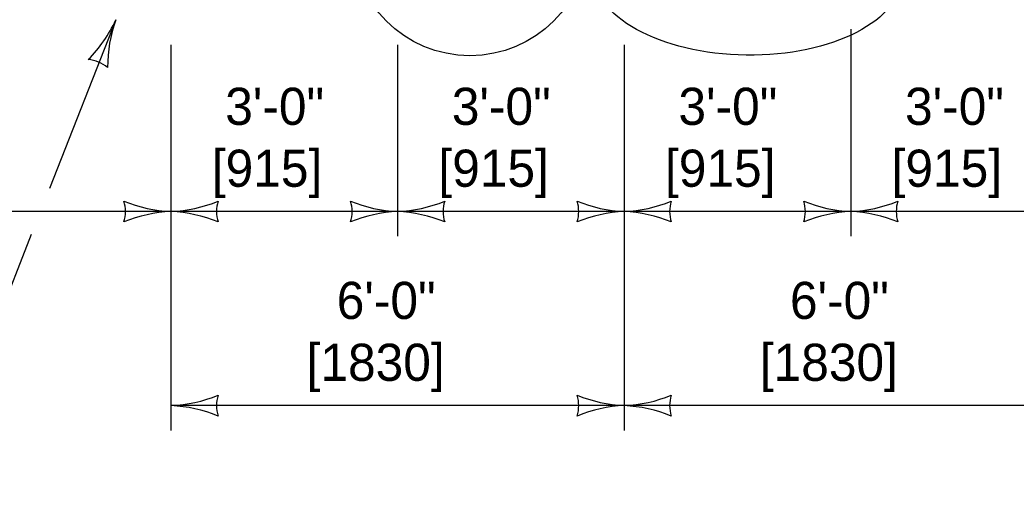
# Model space of a CAD drawing. Extents: x 49991.4 to 50021, y 49987.6 to 50011.4.
# Drawn here: x 50002.768 to 50004.377, y 49995.962 to 49996.713 of the extents above; entities that cross this region are included whole.
import ezdxf

# ---------------------------------------------------------------- set-up
doc = ezdxf.new("R2010")
doc.units = 0
for name, color, linetype in [('Level 1', 7, 'Continuous'), ('Level 2', 7, 'Continuous'), ('Level 3', 7, 'Continuous')]:
    doc.layers.add(name, color=color, linetype=linetype)

msp = doc.modelspace()

# ---------------------------------------------------------------- linework, layer by layer
at = {"layer": 'Level 1'}
msp.add_circle((50003.4953, 49996.8462), 0.1908, dxfattribs=at)
msp.add_ellipse((50003.9433, 49996.7901), major_axis=(0.2512, -0.0033), ratio=0.532586, dxfattribs=at)
at = {"layer": 'Level 3'}
for p, q in [((50002.9231, 49996.7132), (50002.8161, 49996.4409)), ((50004.1104, 49996.6984), (50004.1104, 49996.3637)), ((50003.0124, 49996.6732), (50003.0124, 49996.0502)), ((50003.3784, 49996.6732), (50003.3784, 49996.3637)), ((50003.7444, 49996.6732), (50003.7444, 49996.0502)), ((50003.0124, 49996.4037), (50002.2804, 49996.4037)), ((50003.3784, 49996.4037), (50003.0124, 49996.4037)), ((50003.7444, 49996.4037), (50003.3784, 49996.4037)), ((50004.1104, 49996.4037), (50003.7444, 49996.4037)), ((50004.4764, 49996.4037), (50004.1104, 49996.4037)), ((50002.7868, 49996.3665), (50002.6279, 49995.9618)), ((50003.7444, 49996.0902), (50003.0124, 49996.0902)), ((50004.4764, 49996.0902), (50003.7444, 49996.0902))]:
    msp.add_line(p, q, dxfattribs=at)
for centre, radius, start, end in [((50002.7209, 49996.8056), 0.2223, 315.2605, 335.444), ((50003.1429, 49996.636), 0.233, 160.6318, 179.8816), ((50002.8747, 49996.5945), 0.0548, 49.9433, 85.6656), ((50002.8842, 49996.4037), 0.0548, 342.1388, 17.8612), ((50003.0239, 49996.6364), 0.233, 247.9228, 267.1727), ((50003.0032, 49996.6258), 0.2223, 272.3605, 292.544), ((50003.1406, 49996.4037), 0.0548, 162.1388, 197.8612), ((50003.2502, 49996.4037), 0.0548, 342.1388, 17.8612), ((50003.3899, 49996.6364), 0.233, 247.9228, 267.1727), ((50003.3692, 49996.6258), 0.2223, 272.3605, 292.544), ((50003.5066, 49996.4037), 0.0548, 162.1388, 197.8612), ((50003.6162, 49996.4037), 0.0548, 342.1388, 17.8612), ((50003.7559, 49996.6364), 0.233, 247.9228, 267.1727), ((50003.7352, 49996.6258), 0.2223, 272.3605, 292.544), ((50003.8726, 49996.4037), 0.0548, 162.1388, 197.8612), ((50003.9822, 49996.4037), 0.0548, 342.1388, 17.8612), ((50004.1219, 49996.6364), 0.233, 247.9228, 267.1727), ((50004.1012, 49996.6258), 0.2223, 272.3605, 292.544), ((50004.2386, 49996.4037), 0.0548, 162.1388, 197.8612), ((50003.0216, 49996.1815), 0.2223, 92.3605, 112.544), ((50003.0009, 49996.171), 0.233, 67.9228, 87.1727), ((50003.3876, 49996.1815), 0.2223, 92.3605, 112.544), ((50003.3669, 49996.171), 0.233, 67.9228, 87.1727), ((50003.7536, 49996.1815), 0.2223, 92.3605, 112.544), ((50003.7329, 49996.171), 0.233, 67.9228, 87.1727), ((50004.1196, 49996.1815), 0.2223, 92.3605, 112.544), ((50004.0989, 49996.171), 0.233, 67.9228, 87.1727), ((50003.0032, 49996.3124), 0.2223, 272.3605, 292.544), ((50003.1406, 49996.0902), 0.0548, 162.1388, 197.8612), ((50003.6162, 49996.0902), 0.0548, 342.1388, 17.8612), ((50003.7559, 49996.3229), 0.233, 247.9228, 267.1727), ((50003.7352, 49996.3124), 0.2223, 272.3605, 292.544), ((50003.8726, 49996.0902), 0.0548, 162.1388, 197.8612), ((50003.0009, 49995.8575), 0.233, 67.9228, 87.1727), ((50003.7536, 49995.8681), 0.2223, 92.3605, 112.544), ((50003.7329, 49995.8575), 0.233, 67.9228, 87.1727)]:
    msp.add_arc(centre, radius, start, end, dxfattribs=at)

# ---------------------------------------------------------------- texts
at = {"layer": 'Level 2'}
for s, p in [('3\'-0"', (50003.1, 49996.5437)), ('3\'-0"', (50003.466, 49996.5437)), ('3\'-0"', (50003.832, 49996.5437)), ('3\'-0"', (50004.198, 49996.5437)), ('[915]', (50003.0783, 49996.4437)), ('[915]', (50003.4443, 49996.4437)), ('[915]', (50003.8103, 49996.4437)), ('[915]', (50004.1763, 49996.4437)), ('6\'-0"', (50003.2801, 49996.2302)), ('6\'-0"', (50004.0121, 49996.2302)), ('[1830]', (50003.2314, 49996.1302)), ('[1830]', (50003.9634, 49996.1302))]:
    msp.add_text(s, height=0.06, dxfattribs=at).set_placement(p)

doc.saveas('drawing.dxf')
